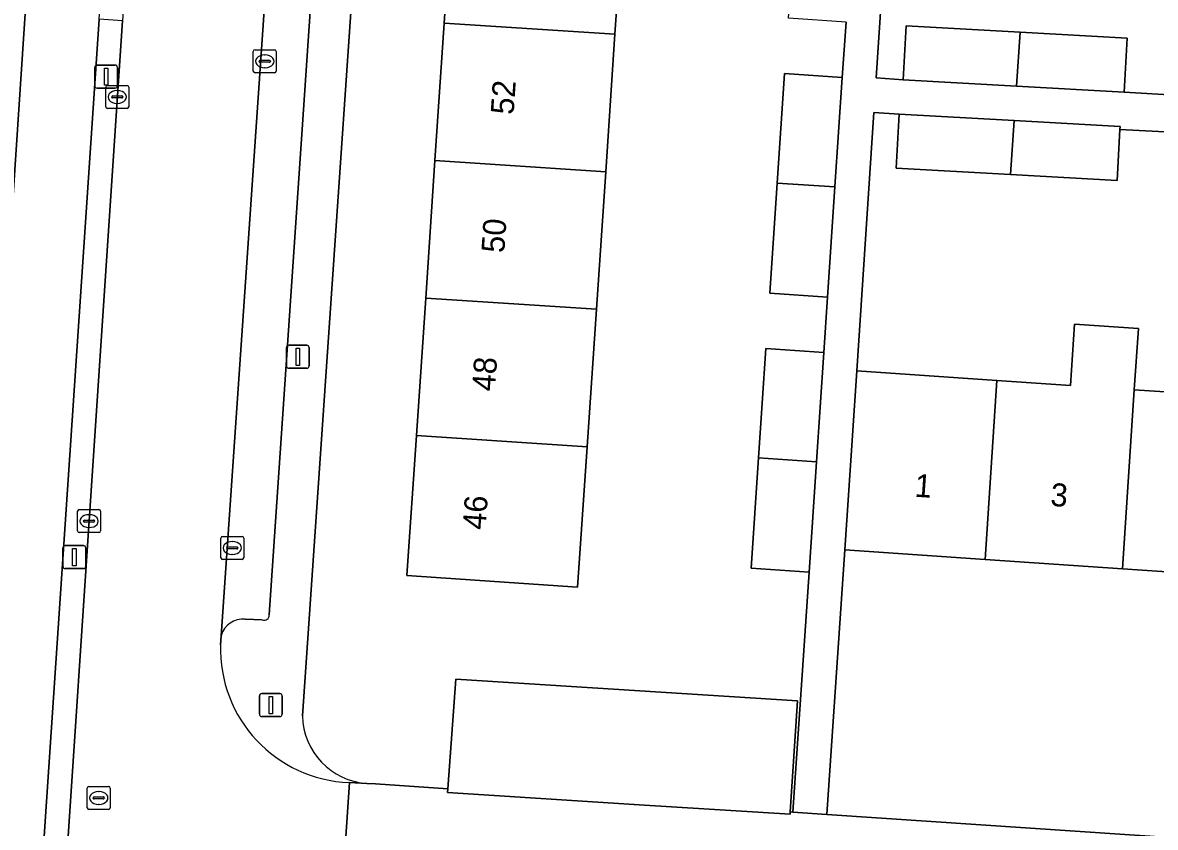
# Model space of a CAD drawing. Extents: x 161848 to 162726, y 385382 to 386521.
# Drawn here: x 162027.96 to 162077.27, y 385929.14 to 385964.19 of the extents above; entities that cross this region are included whole.
import ezdxf

# ---------------------------------------------------------------- set-up
doc = ezdxf.new("R2010")
doc.units = 0
for name, color, linetype in [('IMGEO_Erf', 7, 'Continuous'), ('IMGEO_Fietspad_gesloten', 7, 'Continuous'), ('IMGEO_Groenvoorziening', 7, 'Continuous'), ('IMGEO_Kolk', 7, 'Continuous'), ('IMGEO_Lichtmast', 7, 'Continuous'), ('IMGEO_Pand', 7, 'Continuous'), ('IMGEO_Pand_nummerreeks', 7, 'Continuous'), ('IMGEO_Parkeervlak_open', 7, 'Continuous'), ('IMGEO_Rijbaan_lokaal_open', 7, 'Continuous'), ('IMGEO_Rioolput', 7, 'Continuous'), ('IMGEO_Verkeerseiland_open', 7, 'Continuous'), ('IMGEO_Voetpad_open', 7, 'Continuous'), ('IMGEO_Woonerf_open', 7, 'Continuous')]:
    doc.layers.add(name, color=color, linetype=linetype)

msp = doc.modelspace()

# ---------------------------------------------------------------- linework, layer by layer
at = {"layer": 'IMGEO_Erf'}
for points in [[(162061.127, 385961.967), (162063.64, 385961.799), (162063.811, 385964.208), (162061.298, 385964.376), (162061.618, 385969.185), (162061.935, 385973.941), (162064.448, 385973.773), (162064.553, 385976.102), (162062.135, 385976.263), (162062.47, 385981.281), (162064.888, 385981.12), (162065.312, 385987.466), (162053.355, 385988.257), (162049.375, 385988.473), (162046.839, 385988.641)], [(162043.697, 385985.789), (162040.143, 385933.992)], [(162077.801, 385969.793), (162071.816, 385970.201), (162072.024, 385973.255), (162065.894, 385973.665), (162065.112, 385961.78), (162066.294, 385961.702), (162066.427, 385964.056), (162071.379, 385963.776), (162076.044, 385963.512), (162075.911, 385961.158), (162078.358, 385961.02)], [(162042.949, 385931.049), (162043.317, 385931.03), (162046.474, 385930.817), (162046.826, 385935.595), (162061.69, 385934.656), (162061.373, 385929.812), (162061.492, 385929.804), (162062.195, 385940.26), (162059.682, 385940.428), (162060.002, 385945.229), (162060.319, 385949.993), (162062.832, 385949.825), (162063.003, 385952.234), (162060.49, 385952.402), (162060.809, 385957.199), (162061.127, 385961.967)], [(162078.246, 385959.398), (162075.729, 385959.54), (162075.603, 385957.309), (162070.964, 385957.572), (162065.986, 385957.853), (162066.119, 385960.207), (162065.014, 385960.28), (162064.273, 385949.017), (162070.373, 385948.605), (162073.569, 385948.39), (162073.749, 385951.058), (162076.53, 385950.87), (162076.352, 385948.202), (162082.354, 385947.797)]]:
    msp.add_lwpolyline(points, dxfattribs=at)
for points in [[(162053.343, 385957.691), (162052.94, 385951.71), (162052.535, 385945.719), (162052.123, 385939.607), (162044.693, 385940.108), (162045.105, 385946.207), (162045.509, 385952.194), (162045.913, 385958.181), (162046.317, 385964.168), (162046.721, 385970.155), (162047.125, 385976.142), (162047.541, 385982.308), (162052.231, 385981.992), (162052.488, 385985.804), (162056.669, 385985.523), (162056.412, 385981.711), (162054.971, 385981.807), (162054.555, 385975.643), (162057.43, 385975.45), (162057.027, 385969.484), (162056.236, 385969.535), (162056.027, 385966.449), (162053.944, 385966.589), (162053.748, 385963.681)], [(162111.951, 385937.967), (162105.776, 385938.384), (162099.785, 385938.788), (162093.802, 385939.192), (162087.814, 385939.596), (162081.834, 385939.999), (162075.835, 385940.404), (162069.859, 385940.808), (162063.747, 385941.22), (162062.973, 385929.704), (162111.178, 385926.464)]]:
    msp.add_lwpolyline(points, close=True, dxfattribs=at)
msp.add_arc((162043.16, 385934.06), 3.018, 181.285, 265.9848, dxfattribs=at)
at = {"layer": 'IMGEO_Fietspad_gesloten'}
for points in [[(162025.665, 385880.852), (162031.29, 385964.339), (162032.419, 385981.182), (162033.303, 385994.07), (162034.41, 386011.138)], [(162030.355, 385998.641), (162028.943, 385977.582), (162028.188, 385966.32), (162028.131, 385965.466), (162026.762, 385945.023)]]:
    msp.add_lwpolyline(points, dxfattribs=at)
at = {"layer": 'IMGEO_Groenvoorziening'}
msp.add_lwpolyline([(162023.745, 385965.795), (162022.388, 385945.316), (162026.762, 385945.023), (162028.131, 385965.466), (162027.788, 385965.496)], dxfattribs=at)
at = {"layer": 'IMGEO_Kolk'}
for p, q in [((162038.004, 385962.078), (162038.004, 385962.93)), ((162038.079, 385963.004), (162038.931, 385963.004)), ((162038.492, 385962.784), (162038.517, 385962.784)), ((162039.005, 385962.93), (162039.005, 385962.078)), ((162038.263, 385962.498), (162038.263, 385962.51)), ((162038.701, 385962.461), (162038.303, 385962.461)), ((162038.306, 385962.547), (162038.704, 385962.547)), ((162038.515, 385962.224), (162038.49, 385962.224)), ((162038.747, 385962.51), (162038.747, 385962.498)), ((162038.931, 385962.004), (162038.079, 385962.004)), ((162031.582, 385960.526), (162031.582, 385961.378)), ((162031.657, 385961.452), (162032.509, 385961.452)), ((162032.07, 385961.232), (162032.095, 385961.232)), ((162032.583, 385961.378), (162032.583, 385960.526)), ((162031.841, 385960.946), (162031.841, 385960.958)), ((162032.279, 385960.909), (162031.881, 385960.909)), ((162031.884, 385960.995), (162032.282, 385960.995)), ((162032.093, 385960.672), (162032.068, 385960.672)), ((162032.325, 385960.958), (162032.325, 385960.946)), ((162032.509, 385960.452), (162031.657, 385960.452)), ((162030.354, 385942.051), (162030.354, 385942.903)), ((162030.429, 385942.977), (162031.281, 385942.977)), ((162031.355, 385942.903), (162031.355, 385942.051)), ((162030.613, 385942.471), (162030.613, 385942.483)), ((162031.051, 385942.434), (162030.653, 385942.434)), ((162030.656, 385942.52), (162031.054, 385942.52)), ((162030.842, 385942.757), (162030.867, 385942.757)), ((162031.097, 385942.483), (162031.097, 385942.471)), ((162031.281, 385941.977), (162030.429, 385941.977)), ((162030.865, 385942.197), (162030.84, 385942.197)), ((162036.59, 385940.881), (162036.59, 385941.733)), ((162036.665, 385941.807), (162037.517, 385941.807)), ((162037.078, 385941.587), (162037.103, 385941.587)), ((162037.591, 385941.733), (162037.591, 385940.881)), ((162036.849, 385941.301), (162036.849, 385941.313)), ((162037.287, 385941.264), (162036.889, 385941.264)), ((162036.892, 385941.35), (162037.29, 385941.35)), ((162037.101, 385941.027), (162037.076, 385941.027)), ((162037.333, 385941.313), (162037.333, 385941.301)), ((162037.517, 385940.807), (162036.665, 385940.807))]:
    msp.add_line(p, q, dxfattribs=at)
for points in [[(162038.004, 385962.078), (162038.004, 385962.93)], [(162038.079, 385963.004), (162038.931, 385963.004)], [(162039.005, 385962.93), (162039.005, 385962.078)], [(162038.931, 385962.004), (162038.079, 385962.004)], [(162031.582, 385960.526), (162031.582, 385961.378)], [(162031.657, 385961.452), (162032.509, 385961.452)], [(162032.583, 385961.378), (162032.583, 385960.526)], [(162032.509, 385960.452), (162031.657, 385960.452)], [(162030.354, 385942.051), (162030.354, 385942.903)], [(162030.429, 385942.977), (162031.281, 385942.977)], [(162031.355, 385942.903), (162031.355, 385942.051)], [(162031.281, 385941.977), (162030.429, 385941.977)], [(162036.59, 385940.881), (162036.59, 385941.733)], [(162036.665, 385941.807), (162037.517, 385941.807)], [(162037.591, 385941.733), (162037.591, 385940.881)], [(162037.517, 385940.807), (162036.665, 385940.807)]]:
    msp.add_lwpolyline(points, dxfattribs=at)
for centre, radius, start, end in [((162038.081, 385962.928), 0.0765, 91.552, 178.448), ((162038.081, 385962.928), 0.0765, 91.552, 178.448), ((162038.929, 385962.928), 0.0765, 1.552, 88.448), ((162038.929, 385962.928), 0.0765, 1.552, 88.448), ((162038.303, 385962.507), 0.0403, 85.8775, 175.7526), ((162038.3, 385962.497), 0.0366, 178.938, 274.7102), ((162038.704, 385962.504), 0.043, 264.8664, 352.4533), ((162038.708, 385962.509), 0.0386, 1.7309, 96.639), ((162038.081, 385962.08), 0.0765, 181.552, 268.448), ((162038.081, 385962.08), 0.0765, 181.552, 268.448), ((162038.929, 385962.08), 0.0765, 271.552, 358.448), ((162038.929, 385962.08), 0.0765, 271.552, 358.448), ((162031.659, 385961.376), 0.0765, 91.552, 178.448), ((162031.659, 385961.376), 0.0765, 91.552, 178.448), ((162032.507, 385961.376), 0.0765, 1.552, 88.448), ((162032.507, 385961.376), 0.0765, 1.552, 88.448), ((162031.881, 385960.955), 0.0403, 85.8775, 175.7526), ((162031.878, 385960.945), 0.0366, 178.938, 274.7102), ((162032.282, 385960.952), 0.043, 264.8664, 352.4533), ((162032.286, 385960.957), 0.0386, 1.7309, 96.639), ((162031.659, 385960.528), 0.0765, 181.552, 268.448), ((162031.659, 385960.528), 0.0765, 181.552, 268.448), ((162032.507, 385960.528), 0.0765, 271.552, 358.448), ((162032.507, 385960.528), 0.0765, 271.552, 358.448), ((162030.431, 385942.901), 0.0765, 91.552, 178.448), ((162030.431, 385942.901), 0.0765, 91.552, 178.448), ((162031.279, 385942.901), 0.0765, 1.552, 88.448), ((162031.279, 385942.901), 0.0765, 1.552, 88.448), ((162030.653, 385942.48), 0.0403, 85.8775, 175.7526), ((162030.65, 385942.47), 0.0366, 178.938, 274.7102), ((162031.054, 385942.477), 0.043, 264.8664, 352.4533), ((162031.058, 385942.482), 0.0386, 1.7309, 96.639), ((162030.431, 385942.053), 0.0765, 181.552, 268.448), ((162030.431, 385942.053), 0.0765, 181.552, 268.448), ((162031.279, 385942.053), 0.0765, 271.552, 358.448), ((162031.279, 385942.053), 0.0765, 271.552, 358.448), ((162036.667, 385941.731), 0.0765, 91.552, 178.448), ((162036.667, 385941.731), 0.0765, 91.552, 178.448), ((162037.515, 385941.731), 0.0765, 1.552, 88.448), ((162037.515, 385941.731), 0.0765, 1.552, 88.448), ((162036.889, 385941.31), 0.0403, 85.8775, 175.7526), ((162036.886, 385941.3), 0.0366, 178.938, 274.7102), ((162037.29, 385941.307), 0.043, 264.8664, 352.4533), ((162037.294, 385941.312), 0.0386, 1.7309, 96.639), ((162036.667, 385940.883), 0.0765, 181.552, 268.448), ((162036.667, 385940.883), 0.0765, 181.552, 268.448), ((162037.515, 385940.883), 0.0765, 271.552, 358.448), ((162037.515, 385940.883), 0.0765, 271.552, 358.448)]:
    msp.add_arc(centre, radius, start, end, dxfattribs=at)
for centre, major_axis, ratio, start_param, end_param in [((162038.491, 385962.504), (-0.387, 0.002), 0.722429, 4.712389, 7.853982), ((162038.516, 385962.504), (-0.39, 0.002), 0.717154, 1.570796, 4.712389), ((162032.069, 385960.952), (-0.387, 0.002), 0.722429, 4.712389, 7.853982), ((162032.094, 385960.952), (-0.39, 0.002), 0.717154, 1.570796, 4.712389), ((162030.841, 385942.477), (-0.387, 0.002), 0.722429, 4.712389, 7.853982), ((162030.866, 385942.477), (-0.39, 0.002), 0.717154, 1.570796, 4.712389), ((162037.077, 385941.307), (-0.387, 0.002), 0.722429, 4.712389, 7.853982), ((162037.102, 385941.307), (-0.39, 0.002), 0.717154, 1.570796, 4.712389)]:
    msp.add_ellipse(centre, major_axis=major_axis, ratio=ratio, start_param=start_param, end_param=end_param, dxfattribs=at)
at = {"layer": 'IMGEO_Lichtmast'}
for p, q in [((162031.102, 385961.437), (162031.102, 385962.237)), ((162031.102, 385962.237), (162031.102, 385961.437)), ((162031.202, 385962.337), (162031.992, 385962.337)), ((162031.992, 385962.337), (162031.202, 385962.337)), ((162032.092, 385962.237), (162032.092, 385961.437)), ((162032.092, 385961.437), (162032.092, 385962.237)), ((162031.992, 385961.337), (162031.202, 385961.337)), ((162031.202, 385961.337), (162031.992, 385961.337)), ((162039.444, 385949.234), (162039.444, 385950.034)), ((162039.444, 385950.034), (162039.444, 385949.234)), ((162039.544, 385950.134), (162040.334, 385950.134)), ((162040.334, 385950.134), (162039.544, 385950.134)), ((162040.434, 385950.034), (162040.434, 385949.234)), ((162040.434, 385949.234), (162040.434, 385950.034)), ((162040.334, 385949.134), (162039.544, 385949.134)), ((162039.544, 385949.134), (162040.334, 385949.134)), ((162029.719, 385940.508), (162029.719, 385941.308)), ((162029.719, 385941.308), (162029.719, 385940.508)), ((162029.819, 385941.408), (162030.609, 385941.408)), ((162030.609, 385941.408), (162029.819, 385941.408)), ((162030.709, 385941.308), (162030.709, 385940.508)), ((162030.709, 385940.508), (162030.709, 385941.308)), ((162030.609, 385940.408), (162029.819, 385940.408)), ((162029.819, 385940.408), (162030.609, 385940.408)), ((162038.27, 385934.064), (162038.27, 385934.864)), ((162038.27, 385934.864), (162038.27, 385934.064)), ((162038.37, 385934.964), (162039.16, 385934.964)), ((162039.16, 385934.964), (162038.37, 385934.964)), ((162039.26, 385934.864), (162039.26, 385934.064)), ((162039.26, 385934.064), (162039.26, 385934.864)), ((162039.16, 385933.964), (162038.37, 385933.964)), ((162038.37, 385933.964), (162039.16, 385933.964))]:
    msp.add_line(p, q, dxfattribs=at)
for points in [[(162031.522, 385962.212), (162031.672, 385962.212), (162031.672, 385961.462), (162031.522, 385961.462), (162031.522, 385962.212)], [(162039.864, 385950.009), (162040.014, 385950.009), (162040.014, 385949.259), (162039.864, 385949.259), (162039.864, 385950.009)], [(162030.139, 385941.283), (162030.289, 385941.283), (162030.289, 385940.533), (162030.139, 385940.533), (162030.139, 385941.283)], [(162038.69, 385934.839), (162038.84, 385934.839), (162038.84, 385934.089), (162038.69, 385934.089), (162038.69, 385934.839)]]:
    msp.add_lwpolyline(points, dxfattribs=at)
for centre, start, end in [((162031.202, 385962.237), 90, 180), ((162031.202, 385962.237), 90, 180), ((162031.992, 385962.237), 0, 90), ((162031.992, 385962.237), 360, 90), ((162031.202, 385961.437), 180, 270), ((162031.202, 385961.437), 180, 270), ((162031.992, 385961.437), 270, 0), ((162031.992, 385961.437), 270, 0), ((162039.544, 385950.034), 90, 180), ((162039.544, 385950.034), 90, 180), ((162040.334, 385950.034), 0, 90), ((162040.334, 385950.034), 360, 90), ((162039.544, 385949.234), 180, 270), ((162039.544, 385949.234), 180, 270), ((162040.334, 385949.234), 270, 0), ((162040.334, 385949.234), 270, 0), ((162029.819, 385941.308), 90, 180), ((162029.819, 385941.308), 90, 180), ((162030.609, 385941.308), 0, 90), ((162030.609, 385941.308), 360, 90), ((162029.819, 385940.508), 180, 270), ((162029.819, 385940.508), 180, 270), ((162030.609, 385940.508), 270, 0), ((162030.609, 385940.508), 270, 0), ((162038.37, 385934.864), 90, 180), ((162038.37, 385934.864), 90, 180), ((162039.16, 385934.864), 0, 90), ((162039.16, 385934.864), 360, 90), ((162038.37, 385934.064), 180, 270), ((162038.37, 385934.064), 180, 270), ((162039.16, 385934.064), 270, 0), ((162039.16, 385934.064), 270, 0)]:
    msp.add_arc(centre, 0.1, start, end, dxfattribs=at)
at = {"layer": 'IMGEO_Pand'}
for points in [[(162056.236, 385969.535), (162054.152, 385969.671), (162046.721, 385970.155), (162046.317, 385964.168), (162053.748, 385963.681), (162053.944, 385966.589), (162056.027, 385966.449)], [(162046.317, 385964.168), (162045.913, 385958.181), (162053.343, 385957.691), (162053.748, 385963.681)], [(162066.427, 385964.056), (162066.294, 385961.702), (162071.219, 385961.424), (162071.379, 385963.776)], [(162075.911, 385961.158), (162076.044, 385963.512), (162071.379, 385963.776), (162071.219, 385961.424)], [(162063.64, 385961.799), (162061.127, 385961.967), (162060.809, 385957.199), (162063.323, 385957.033)], [(162066.119, 385960.207), (162065.986, 385957.853), (162070.964, 385957.572), (162071.119, 385959.925)], [(162075.729, 385959.54), (162075.736, 385959.663), (162071.119, 385959.925), (162070.964, 385957.572), (162075.603, 385957.309)], [(162045.913, 385958.181), (162045.509, 385952.194), (162052.94, 385951.71), (162053.343, 385957.691)], [(162060.49, 385952.402), (162063.003, 385952.234), (162063.323, 385957.033), (162060.809, 385957.199)], [(162052.535, 385945.719), (162052.94, 385951.71), (162045.509, 385952.194), (162045.105, 385946.207)], [(162070.373, 385948.605), (162069.859, 385940.808), (162075.835, 385940.404), (162076.352, 385948.202), (162076.53, 385950.87), (162073.749, 385951.058), (162073.569, 385948.39)], [(162062.515, 385945.064), (162062.832, 385949.825), (162060.319, 385949.993), (162060.002, 385945.229)], [(162070.373, 385948.605), (162064.273, 385949.017), (162064.084, 385946.209), (162063.747, 385941.22), (162069.859, 385940.808)], [(162082.354, 385947.797), (162076.352, 385948.202), (162075.835, 385940.404), (162081.834, 385939.999)], [(162052.535, 385945.719), (162045.105, 385946.207), (162044.693, 385940.108), (162052.123, 385939.607)], [(162060.002, 385945.229), (162059.682, 385940.428), (162062.195, 385940.26), (162062.515, 385945.064)], [(162061.69, 385934.656), (162046.826, 385935.595), (162046.474, 385930.817), (162046.462, 385930.654), (162055.027, 385930.112), (162061.366, 385929.711), (162061.373, 385929.812)]]:
    msp.add_lwpolyline(points, close=True, dxfattribs=at)
at = {"layer": 'IMGEO_Parkeervlak_open'}
for points in [[(162039.579, 385980.773), (162036.606, 385937.482)], [(162038.701, 385938.4), (162041.478, 385979.423)], [(162037.657, 385938.203), (162038.395, 385938.174)]]:
    msp.add_lwpolyline(points, dxfattribs=at)
for centre, radius, start, end in [((162037.555, 385937.225), 0.983, 84.043, 164.8583), ((162038.478, 385938.382), 0.224, 248.2782, 4.6182)]:
    msp.add_arc(centre, radius, start, end, dxfattribs=at)
at = {"layer": 'IMGEO_Rijbaan_lokaal_open'}
for points in [[(162041.102, 386004.154), (162041.12, 386004.571), (162045.689, 386072.893), (162046.97, 386091.978), (162040.968, 386092.437), (162035.482, 386011.093), (162034.343, 385994.018), (162033.471, 385981.124), (162032.304, 385964.271), (162028.465, 385906.543), (162026.839, 385883.258), (162032.937, 385882.841), (162035.569, 385921.295)], [(162036.579, 385937.095), (162036.606, 385937.482), (162039.579, 385980.773), (162039.981, 385986.928), (162040.057, 385988.095)], [(162041.849, 385925.93), (162042.191, 385931.089)]]:
    msp.add_lwpolyline(points, dxfattribs=at)
msp.add_arc((162042.404, 385936.913), 5.828, 178.2123, 267.9031, dxfattribs=at)
at = {"layer": 'IMGEO_Rioolput'}
for p, q in [((162030.777, 385929.994), (162030.777, 385930.846)), ((162030.852, 385930.92), (162031.704, 385930.92)), ((162031.265, 385930.7), (162031.29, 385930.7)), ((162031.778, 385930.846), (162031.778, 385929.994)), ((162031.036, 385930.414), (162031.036, 385930.426)), ((162031.474, 385930.377), (162031.076, 385930.377)), ((162031.079, 385930.463), (162031.477, 385930.463)), ((162031.288, 385930.14), (162031.263, 385930.14)), ((162031.52, 385930.426), (162031.52, 385930.414)), ((162031.704, 385929.92), (162030.852, 385929.92))]:
    msp.add_line(p, q, dxfattribs=at)
for points in [[(162030.777, 385929.994), (162030.777, 385930.846)], [(162030.852, 385930.92), (162031.704, 385930.92)], [(162031.778, 385930.846), (162031.778, 385929.994)], [(162031.704, 385929.92), (162030.852, 385929.92)]]:
    msp.add_lwpolyline(points, dxfattribs=at)
for centre, radius, start, end in [((162030.854, 385930.844), 0.0765, 91.552, 178.448), ((162030.854, 385930.844), 0.0765, 91.552, 178.448), ((162031.702, 385930.844), 0.0765, 1.552, 88.448), ((162031.702, 385930.844), 0.0765, 1.552, 88.448), ((162031.076, 385930.423), 0.0403, 85.8775, 175.7526), ((162031.073, 385930.413), 0.0366, 178.938, 274.7102), ((162031.477, 385930.42), 0.043, 264.8664, 352.4533), ((162031.481, 385930.425), 0.0386, 1.7309, 96.639), ((162030.854, 385929.996), 0.0765, 181.552, 268.448), ((162030.854, 385929.996), 0.0765, 181.552, 268.448), ((162031.702, 385929.996), 0.0765, 271.552, 358.448), ((162031.702, 385929.996), 0.0765, 271.552, 358.448)]:
    msp.add_arc(centre, radius, start, end, dxfattribs=at)
for centre, major_axis, ratio, start_param, end_param in [((162031.264, 385930.42), (-0.387, 0.002), 0.722429, 4.712389, 7.853982), ((162031.289, 385930.42), (-0.39, 0.002), 0.717154, 1.570796, 4.712389)]:
    msp.add_ellipse(centre, major_axis=major_axis, ratio=ratio, start_param=start_param, end_param=end_param, dxfattribs=at)
at = {"layer": 'IMGEO_Verkeerseiland_open'}
msp.add_lwpolyline([(162031.29, 385964.339), (162025.665, 385880.852), (162026.657, 385880.78), (162026.839, 385883.258), (162028.465, 385906.543), (162032.304, 385964.271)], close=True, dxfattribs=at)
at = {"layer": 'IMGEO_Voetpad_open'}
for points in [[(162040.143, 385933.992), (162043.697, 385985.789)], [(162041.478, 385979.423), (162038.701, 385938.4)], [(162078.358, 385961.02), (162075.911, 385961.158), (162071.219, 385961.424), (162066.294, 385961.702), (162065.112, 385961.78), (162065.894, 385973.665)], [(162063.811, 385964.208), (162063.64, 385961.799), (162063.323, 385957.033), (162063.003, 385952.234), (162062.832, 385949.825), (162062.515, 385945.064), (162062.195, 385940.26), (162061.492, 385929.804), (162062.973, 385929.704), (162063.747, 385941.22), (162064.084, 385946.209), (162064.273, 385949.017), (162065.014, 385960.28), (162066.119, 385960.207), (162071.119, 385959.925), (162075.736, 385959.663), (162075.729, 385959.54), (162078.246, 385959.398)], [(162038.395, 385938.174), (162037.657, 385938.203)], [(162036.606, 385937.482), (162036.579, 385937.095)], [(162042.191, 385931.089), (162042.949, 385931.049)]]:
    msp.add_lwpolyline(points, dxfattribs=at)
for centre, radius, start, end in [((162037.555, 385937.225), 0.983, 84.043, 164.8583), ((162038.478, 385938.382), 0.224, 248.2782, 4.6182), ((162042.404, 385936.913), 5.828, 178.2123, 267.9031), ((162043.16, 385934.06), 3.018, 181.285, 265.9848)]:
    msp.add_arc(centre, radius, start, end, dxfattribs=at)
at = {"layer": 'IMGEO_Woonerf_open'}
msp.add_lwpolyline([(162112.645, 385926.365), (162111.178, 385926.464), (162062.973, 385929.704), (162061.492, 385929.804), (162061.373, 385929.812), (162061.366, 385929.711), (162055.027, 385930.112), (162046.462, 385930.654), (162046.474, 385930.817), (162043.317, 385931.03), (162042.949, 385931.049), (162042.191, 385931.089), (162041.849, 385925.93), (162042.942, 385925.829), (162046.771, 385925.731), (162054.686, 385925.183), (162062.576, 385924.706), (162110.864, 385921.497), (162112.048, 385921.418), (162123.446, 385920.647), (162129.418, 385920.249), (162134.187, 385919.947)], dxfattribs=at)

# ---------------------------------------------------------------- texts
at = {"layer": 'IMGEO_Pand_nummerreeks'}
for s, rotation, p in [('52', 86.1391, (162049.333, 385960.16)), ('50', 86.1391, (162048.928, 385954.137)), ('48', 86.1391, (162048.521, 385948.109)), ('1', 356.1393, (162066.768, 385943.542)), ('3', 356.1393, (162072.681, 385943.143)), ('46', 86.1385, (162048.114, 385942.077))]:
    msp.add_text(s, height=1, rotation=rotation, dxfattribs=at).set_placement(p)

doc.saveas('drawing.dxf')
